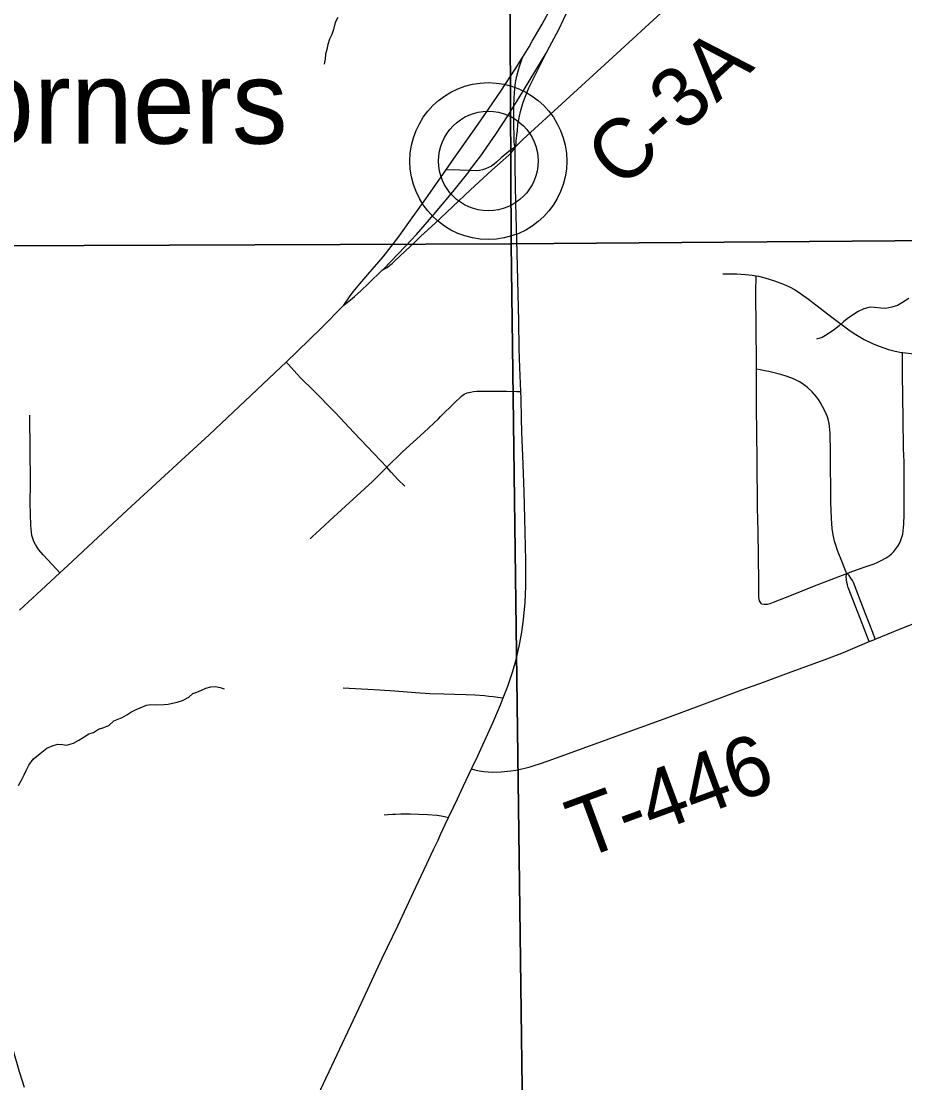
# Model space of a CAD drawing. Extents: x 0 to 34, y 0 to 22.
# Drawn here: x 6.446 to 7.284, y 17.466 to 18.473 of the extents above; entities that cross this region are included whole.
import ezdxf

# ---------------------------------------------------------------- set-up
doc = ezdxf.new("R2010")
doc.units = 0
for name, color, linetype in [('GM_X_County_Road', 7, 'Continuous'), ('GM_X_County_Road_Text', 7, 'Continuous'), ('GM_X_Interchange_Ramps', 7, 'Continuous'), ('GM_X_Minor_River', 7, 'Continuous'), ('GM_X_Section', 7, 'Continuous'), ('GM_X_State_Route', 7, 'Continuous'), ('GM_X_Township_Road', 7, 'Continuous'), ('GM_X_Township_Road_Text', 7, 'Continuous'), ('GM_X_Unincorporated', 7, 'Continuous'), ('GM_X_Unincorporated_Location', 7, 'Continuous'), ('GM_X_Unincorporated_Text', 7, 'Continuous')]:
    doc.layers.add(name, color=color, linetype=linetype)

msp = doc.modelspace()

# ---------------------------------------------------------------- linework, layer by layer
at = {"layer": 'GM_X_County_Road'}
msp.add_lwpolyline([(6.9143, 18.3538), (6.9217, 18.3612), (7.0032, 18.4357), (7.0604, 18.4882), (7.0903, 18.5154), (7.1541, 18.5743), (7.1635, 18.5838), (7.1761, 18.5962), (7.192, 18.6134), (7.2032, 18.626), (7.2991, 18.7318), (7.3555, 18.794), (7.3689, 18.8087)], dxfattribs=at)
at = {"layer": 'GM_X_Interchange_Ramps'}
for points in [[(6.7883, 18.2371), (6.7929, 18.2397), (6.7956, 18.2419), (6.7976, 18.2435), (6.7999, 18.2457), (6.8202, 18.2648), (6.8249, 18.2695), (6.8385, 18.2819), (6.872, 18.3134), (6.8923, 18.3322), (6.9083, 18.3463), (6.9105, 18.3484), (6.912, 18.3503), (6.9143, 18.3538)], [(6.9143, 18.3538), (6.9099, 18.3509), (6.9066, 18.3481), (6.9012, 18.3437), (6.8967, 18.3396), (6.8943, 18.3377), (6.8918, 18.336), (6.8891, 18.3345), (6.8863, 18.3333), (6.8834, 18.3323), (6.8804, 18.3318), (6.8773, 18.3315), (6.8712, 18.3317), (6.862, 18.3322), (6.8558, 18.3323), (6.8486, 18.3321)]]:
    msp.add_lwpolyline(points, dxfattribs=at)
at = {"layer": 'GM_X_Minor_River'}
for points in [[(6.7463, 18.4769), (6.7437, 18.472), (6.7419, 18.4655), (6.7404, 18.4609), (6.7382, 18.4563), (6.7368, 18.4514), (6.7357, 18.4464), (6.7346, 18.4422), (6.7343, 18.4373), (6.7332, 18.4327)], [(7.2879, 18.2103), (7.2819, 18.2064), (7.277, 18.2037), (7.2717, 18.2021), (7.266, 18.2009), (7.2611, 18.2012), (7.2553, 18.2019), (7.2512, 18.2022), (7.2451, 18.2006), (7.2398, 18.1979), (7.2304, 18.1921), (7.2262, 18.1886), (7.2217, 18.1843), (7.2172, 18.1809), (7.2104, 18.1762), (7.2055, 18.1735), (7.2002, 18.1719)], [(6.4432, 17.7485), (6.4461, 17.7535), (6.4487, 17.7585), (6.4506, 17.7627), (6.4532, 17.7676), (6.4573, 17.7734), (6.4637, 17.7788), (6.4701, 17.7838), (6.4761, 17.7865), (6.4807, 17.7877), (6.4849, 17.7874), (6.4887, 17.7867), (6.4955, 17.7887), (6.5004, 17.7914), (6.5046, 17.7941), (6.5099, 17.7973), (6.5144, 17.7988), (6.5193, 17.8019), (6.5242, 17.8035), (6.5288, 17.8055), (6.5337, 17.8097), (6.5416, 17.8129), (6.5461, 17.8156), (6.5499, 17.8179), (6.5548, 17.8206), (6.5586, 17.8222), (6.5646, 17.8246), (6.5688, 17.8254), (6.5734, 17.8251), (6.5814, 17.8252), (6.5852, 17.8256), (6.5893, 17.8264), (6.5939, 17.8276), (6.5988, 17.8292), (6.6049, 17.8323), (6.6086, 17.8358), (6.6124, 17.837), (6.6169, 17.8389), (6.6211, 17.8409), (6.6256, 17.8421), (6.6302, 17.8425), (6.6344, 17.8415), (6.6382, 17.84)]]:
    msp.add_lwpolyline(points, dxfattribs=at)
at = {"layer": 'GM_X_Section'}
for points in [[(5.7801, 19.2683), (6.9057, 19.2783), (6.9105, 18.2623), (5.7758, 18.2578), (5.7756, 18.2855)], [(6.9057, 19.2783), (7.9079, 19.2721), (7.9217, 18.2701), (6.9105, 18.2623)], [(7.9217, 18.2701), (7.9201, 17.2543), (6.9237, 17.2428), (6.9105, 18.2623)], [(5.7758, 18.2578), (6.9105, 18.2623), (6.9237, 17.2428), (5.7724, 17.2281), (5.7727, 17.3042)]]:
    msp.add_lwpolyline(points, close=True, dxfattribs=at)
at = {"layer": 'GM_X_State_Route'}
for points in [[(6.9438, 18.4431), (6.947, 18.4492), (6.9557, 18.4656), (6.9652, 18.4856), (6.9753, 18.5067), (6.9809, 18.5196), (6.9865, 18.5325), (6.9995, 18.5664), (7.0151, 18.6071), (7.0266, 18.6372), (7.0439, 18.6798), (7.0463, 18.6857), (7.0675, 18.741), (7.1024, 18.8307), (7.1204, 18.877), (7.1254, 18.8899), (7.1312, 18.9049), (7.1377, 18.9218), (7.1398, 18.9272)], [(6.9305, 18.4543), (6.94, 18.4706), (6.9505, 18.4897)], [(6.7518, 18.2039), (6.7573, 18.2119), (6.7608, 18.2167), (6.767, 18.2243), (6.7746, 18.233), (6.7891, 18.2499), (6.8044, 18.2696), (6.8134, 18.2823), (6.8296, 18.305), (6.8486, 18.3321), (6.8564, 18.3433), (6.8815, 18.3788), (6.9009, 18.407), (6.9145, 18.4279), (6.9213, 18.4389), (6.9275, 18.4491), (6.9305, 18.4543)], [(6.9143, 18.3538), (6.9138, 18.3565), (6.9135, 18.3588), (6.913, 18.3811), (6.9132, 18.3929), (6.9132, 18.3935), (6.9136, 18.4059), (6.9147, 18.4151), (6.9158, 18.4213), (6.9174, 18.4273), (6.9184, 18.4303), (6.9213, 18.4389)], [(6.9132, 18.3929), (6.9178, 18.4003), (6.9438, 18.4431)], [(6.9143, 18.3538), (6.9152, 18.3569), (6.9154, 18.3598), (6.9161, 18.365), (6.9165, 18.3694), (6.917, 18.3756), (6.918, 18.3817), (6.9193, 18.3878), (6.922, 18.3967), (6.9225, 18.3981), (6.9273, 18.4101), (6.9308, 18.4172), (6.935, 18.4253), (6.9438, 18.4431)], [(6.7518, 18.2039), (6.7583, 18.2091), (6.7621, 18.2121), (6.7681, 18.2176), (6.7752, 18.2245), (6.7883, 18.2371), (6.7895, 18.2382), (6.8101, 18.2598), (6.8208, 18.2712), (6.8372, 18.2899), (6.8551, 18.3114), (6.8706, 18.3308), (6.8712, 18.3317), (6.8817, 18.3458), (6.8959, 18.3663), (6.9079, 18.3844), (6.9132, 18.3929)], [(6.8436, 17.702), (6.8481, 17.7116), (6.8511, 17.7181), (6.8515, 17.7188), (6.8558, 17.7279), (6.8596, 17.7359), (6.8653, 17.748), (6.8705, 17.7589), (6.8731, 17.7643), (6.8737, 17.7656), (6.8788, 17.7766), (6.8869, 17.7941), (6.8932, 17.8079), (6.9006, 17.825), (6.9031, 17.8316), (6.9073, 17.8426), (6.9121, 17.857), (6.9149, 17.8666), (6.9185, 17.8819), (6.9208, 17.894), (6.9223, 17.9059), (6.9239, 17.922), (6.9246, 17.9376), (6.9246, 17.9619), (6.9236, 18.0016), (6.9228, 18.0272), (6.9217, 18.0614), (6.9206, 18.0833), (6.9205, 18.097), (6.9199, 18.1151), (6.9196, 18.1222), (6.9189, 18.1448), (6.9183, 18.1627), (6.9179, 18.1887), (6.9171, 18.2149), (6.9158, 18.2664), (6.9149, 18.3006), (6.9145, 18.3348), (6.9143, 18.3538)], [(6.4443, 17.9146), (6.4648, 17.9336), (6.4825, 17.9501), (6.4898, 17.9568), (6.5187, 17.9839), (6.5465, 18.0095), (6.6013, 18.0602), (6.6242, 18.0812), (6.692, 18.1452), (6.6971, 18.15), (6.73, 18.1818), (6.7518, 18.2039)], [(6.508, 16.986), (6.5565, 17.089), (6.5715, 17.1205), (6.5896, 17.1601), (6.6081, 17.1994), (6.6293, 17.2444), (6.631, 17.2481), (6.6448, 17.2783), (6.6596, 17.309), (6.69, 17.3741), (6.7091, 17.4152), (6.7251, 17.4496), (6.7686, 17.5424), (6.7883, 17.5846), (6.8031, 17.6154), (6.8201, 17.652), (6.8307, 17.6742), (6.8344, 17.6824), (6.8368, 17.6879), (6.8412, 17.6967), (6.8436, 17.702)]]:
    msp.add_lwpolyline(points, dxfattribs=at)
at = {"layer": 'GM_X_Township_Road'}
for points in [[(7.1114, 18.2336), (7.1247, 18.2336), (7.1329, 18.2332), (7.1391, 18.2326), (7.1429, 18.232)], [(7.1433, 18.1434), (7.1433, 18.1506), (7.1428, 18.1816), (7.1426, 18.2167), (7.1429, 18.232)], [(7.1429, 18.232), (7.1452, 18.2316), (7.1513, 18.2301), (7.1603, 18.2272), (7.1689, 18.2238), (7.1745, 18.2213), (7.1799, 18.2185), (7.1851, 18.2152), (7.1926, 18.2097), (7.2148, 18.1927), (7.2322, 18.1797), (7.2374, 18.1761), (7.2455, 18.1715), (7.2539, 18.1673), (7.2597, 18.165), (7.2686, 18.162), (7.2747, 18.1604), (7.2808, 18.1592), (7.2817, 18.1591)], [(7.2289, 17.9495), (7.2346, 17.9517), (7.2464, 17.9557), (7.2519, 17.9576), (7.2548, 17.9588), (7.2577, 17.9599), (7.261, 17.9614), (7.2664, 17.9644), (7.269, 17.9662), (7.2714, 17.9682), (7.2735, 17.9704), (7.2755, 17.9729), (7.2772, 17.9755), (7.2788, 17.9781), (7.2802, 17.981), (7.2812, 17.9839), (7.282, 17.9869), (7.2825, 17.99), (7.283, 17.9962), (7.2832, 18.0056), (7.2832, 18.0234), (7.2832, 18.0555), (7.2828, 18.068), (7.2823, 18.0961), (7.2819, 18.1386), (7.2818, 18.1522), (7.2817, 18.1591)], [(7.2817, 18.1591), (7.2901, 18.1581), (7.2994, 18.1577), (7.3274, 18.1577), (7.3492, 18.1584)], [(6.8096, 18.0325), (6.8032, 18.0387), (6.7968, 18.0456), (6.7926, 18.0503), (6.7866, 18.0568), (6.7614, 18.0834), (6.744, 18.102), (6.7225, 18.1238), (6.7114, 18.1344), (6.7072, 18.1389), (6.6993, 18.1476), (6.6971, 18.15)], [(7.2185, 17.9765), (7.2174, 17.9801), (7.216, 17.9862), (7.2151, 17.9923), (7.2143, 18.0017), (7.2138, 18.0172), (7.2136, 18.0639), (7.213, 18.0826), (7.2126, 18.0888), (7.2122, 18.0919), (7.2116, 18.0947), (7.2107, 18.098), (7.2082, 18.1037), (7.2038, 18.1119), (7.2021, 18.1145), (7.2002, 18.1171), (7.1961, 18.1217), (7.1915, 18.1259), (7.1865, 18.1297), (7.1839, 18.1313), (7.1783, 18.1341), (7.1722, 18.1364), (7.1665, 18.1382), (7.1549, 18.1412), (7.1513, 18.1419), (7.1467, 18.1428), (7.1433, 18.1434)], [(7.1481, 17.9209), (7.1461, 17.9235), (7.1454, 17.927), (7.1454, 17.9414), (7.1447, 17.9901), (7.1443, 18.0115), (7.144, 18.0579), (7.1434, 18.1073), (7.1433, 18.1434)], [(6.7198, 17.9825), (6.7222, 17.9845), (6.7291, 17.9909), (6.7387, 17.9997), (6.7607, 18.0201), (6.7789, 18.0368), (6.7926, 18.0503), (6.8074, 18.0648), (6.8277, 18.0834), (6.8372, 18.0922), (6.8415, 18.0962), (6.8437, 18.0983), (6.8568, 18.1114), (6.8636, 18.1177), (6.8661, 18.1195), (6.8689, 18.1208), (6.8719, 18.1216), (6.8749, 18.1221), (6.878, 18.1224), (6.8842, 18.1224), (6.8996, 18.1225), (6.9063, 18.1224), (6.916, 18.1222), (6.9196, 18.1222)], [(6.4825, 17.9501), (6.4792, 17.9537), (6.4667, 17.9673), (6.4627, 17.972), (6.4609, 17.9745), (6.4593, 17.9771), (6.4579, 17.9799), (6.4568, 17.9827), (6.456, 17.9857), (6.4555, 17.9888), (6.455, 17.9949), (6.4544, 18.0166), (6.4547, 18.035), (6.4544, 18.0687), (6.4539, 18.0963), (6.454, 18.0998)], [(7.2289, 17.9495), (7.2281, 17.9515), (7.2247, 17.9595), (7.2202, 17.9712), (7.2185, 17.9765)], [(7.1481, 17.9209), (7.1504, 17.9204), (7.1521, 17.9204), (7.1536, 17.9204), (7.1563, 17.9211), (7.1593, 17.9223), (7.1765, 17.9289), (7.1968, 17.9371), (7.2289, 17.9495)], [(7.25, 17.8849), (7.2475, 17.8914), (7.2463, 17.8947), (7.2303, 17.9364), (7.2296, 17.9387), (7.2289, 17.9409), (7.2285, 17.9439), (7.2284, 17.9467), (7.2285, 17.9482), (7.2289, 17.9495)], [(7.2558, 17.8873), (7.2535, 17.8935), (7.2468, 17.9114), (7.2352, 17.941), (7.2342, 17.9429), (7.2328, 17.9452), (7.2311, 17.9476), (7.2301, 17.9486), (7.2289, 17.9495)], [(7.25, 17.8849), (7.2545, 17.8867), (7.2558, 17.8873), (7.2804, 17.8975), (7.3006, 17.9054), (7.3095, 17.9084), (7.3184, 17.911), (7.3275, 17.9131), (7.3366, 17.9147), (7.3489, 17.9164), (7.3675, 17.9183), (7.3892, 17.9202), (7.4202, 17.9231), (7.428, 17.9238)], [(6.8731, 17.7643), (6.8762, 17.7634), (6.8803, 17.7623), (6.8845, 17.7616), (6.8928, 17.761), (6.9012, 17.7613), (6.9104, 17.7623), (6.915, 17.7629), (6.9195, 17.764), (6.9248, 17.7652), (6.9287, 17.7663), (6.9334, 17.7677), (6.9375, 17.769), (6.9457, 17.7718), (6.9537, 17.7747), (7.0182, 17.7981), (7.0592, 17.8129), (7.0913, 17.825), (7.1293, 17.8391), (7.1498, 17.8465), (7.1761, 17.8562), (7.2083, 17.868), (7.2257, 17.8747), (7.25, 17.8849)], [(6.7513, 17.8411), (6.7569, 17.8408), (6.7745, 17.8399), (6.7857, 17.8393), (6.8001, 17.8382), (6.8198, 17.8367), (6.8335, 17.8358), (6.8466, 17.8353), (6.8677, 17.8347), (6.8762, 17.8343), (6.8852, 17.8337), (6.8893, 17.8332), (6.8936, 17.833), (6.9001, 17.832), (6.9031, 17.8316)], [(6.7902, 17.7205), (6.7937, 17.7208), (6.798, 17.7211), (6.801, 17.7214), (6.8058, 17.7215), (6.8099, 17.7215), (6.8147, 17.7215), (6.8313, 17.7209), (6.8404, 17.7203), (6.8442, 17.7198), (6.8474, 17.719), (6.8511, 17.7181)], [(6.4489, 17.462), (6.4443, 17.477), (6.4381, 17.4977), (6.4331, 17.5159), (6.4317, 17.524), (6.4315, 17.5264)]]:
    msp.add_lwpolyline(points, dxfattribs=at)
at = {"layer": 'GM_X_Unincorporated'}
for radius in [0.0744, 0.0472]:
    msp.add_circle((6.8889, 18.3407), radius, dxfattribs=at)
at = {"layer": 'GM_X_Unincorporated_Location'}
msp.add_line((6.8889, 18.3407), (6.8889, 18.3407), dxfattribs=at)

# ---------------------------------------------------------------- texts
at = {"layer": 'GM_X_County_Road_Text'}
msp.add_text('C-3A', height=0.05682, rotation=42.3778, dxfattribs=at).set_placement((7.0149, 18.3126))
at = {"layer": 'GM_X_Township_Road_Text'}
msp.add_text('T-446', height=0.05682, rotation=20.1972, dxfattribs=at).set_placement((6.9774, 17.678))
at = {"layer": 'GM_X_Unincorporated_Text'}
msp.add_text('Burnetts Corners', height=0.078977, rotation=0, dxfattribs=at).set_placement((5.9002, 18.3572))

doc.saveas('drawing.dxf')
